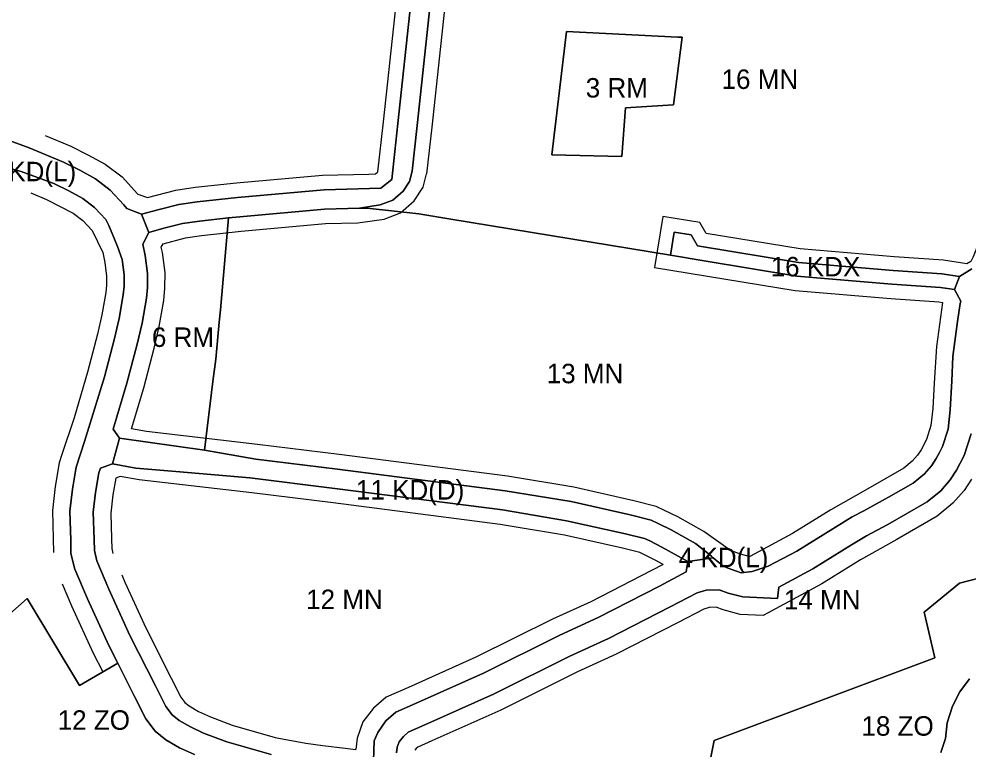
# Model space of a CAD drawing. Extents: x 7418056 to 7420315, y 5537846 to 5539505.
# Drawn here: x 7419326.3 to 7419814.6, y 5538250.2 to 5538625.8 of the extents above; entities that cross this region are included whole.
import ezdxf

# ---------------------------------------------------------------- set-up
doc = ezdxf.new("R2010")
doc.units = 0
for name, color, linetype in [('linie_rozgraniczajace', 7, 'Continuous'), ('linie_zabudowy_nieprzekraczalne', 7, 'Continuous'), ('oznaczenia_przeznaczen', 7, 'Continuous')]:
    doc.layers.add(name, color=color, linetype=linetype)

msp = doc.modelspace()

# ---------------------------------------------------------------- linework, layer by layer
at = {"layer": 'linie_rozgraniczajace'}
for points in [[(7419527.79, 5538634.11), (7419521.09, 5538572.08), (7419517.88, 5538543.33), (7419512.34, 5538538.77), (7419483.13, 5538538.02), (7419438.65, 5538534.06), (7419417.86, 5538531.87), (7419408.44, 5538530.44), (7419398.33, 5538527.89), (7419389.39, 5538525.51), (7419381.7, 5538528.33), (7419380.3, 5538530.33), (7419373.25, 5538537.88), (7419365.65, 5538543.65), (7419357.53, 5538548.07), (7419349.3, 5538552.2), (7419331.61, 5538559.58), (7419319.89, 5538563.81)], [(7419537.73, 5538633.12), (7419531.03, 5538570.98), (7419528.42, 5538547.57), (7419527.08, 5538542.33), (7419523.81, 5538537.29), (7419518.49, 5538532.76), (7419512.01, 5538530.22), (7419501.3, 5538528.51), (7419483.39, 5538528.1), (7419439.88, 5538524.14), (7419434.05, 5538523.53), (7419419.14, 5538521.95), (7419410.42, 5538520.63), (7419400.85, 5538518.22), (7419393.14, 5538516.15), (7419389.39, 5538525.51), (7419398.33, 5538527.89), (7419408.44, 5538530.44), (7419417.86, 5538531.87), (7419438.65, 5538534.06), (7419483.13, 5538538.02), (7419512.34, 5538538.77), (7419517.88, 5538543.33), (7419521.09, 5538572.08), (7419527.79, 5538634.11)], [(7419816.12, 5538497.47), (7419809.77, 5538493.53), (7419800.65, 5538494.85), (7419775.53, 5538496.55), (7419726.97, 5538500.67), (7419675.06, 5538509.2), (7419671.87, 5538514.79), (7419663.05, 5538516.24), (7419661.14, 5538504.39), (7419548.36, 5538522.9), (7419531.9, 5538525.73), (7419505.32, 5538528.6), (7419501.3, 5538528.51), (7419512.01, 5538530.22), (7419518.49, 5538532.76), (7419523.81, 5538537.29), (7419527.08, 5538542.33), (7419528.42, 5538547.57), (7419531.03, 5538570.98), (7419537.73, 5538633.12)], [(7419319.89, 5538563.81), (7419331.61, 5538559.58), (7419349.3, 5538552.2), (7419357.53, 5538548.07), (7419365.65, 5538543.65), (7419373.25, 5538537.88), (7419380.3, 5538530.33), (7419381.7, 5538528.33), (7419389.39, 5538525.51), (7419393.14, 5538516.15), (7419389.95, 5538510.08), (7419391.15, 5538504.22), (7419392.41, 5538495.02), (7419392.33, 5538487.87), (7419391.83, 5538482.39), (7419389.58, 5538469.57), (7419387.14, 5538458.78), (7419381.75, 5538438.65), (7419374.77, 5538414.95), (7419377.93, 5538410.33), (7419374.4, 5538397.3), (7419368.23, 5538395.05), (7419367.46, 5538392.63), (7419365.67, 5538382.53), (7419364.53, 5538372.33), (7419364.93, 5538358.39), (7419365.11, 5538352.68), (7419366.27, 5538347.32), (7419372.54, 5538332.83), (7419383.38, 5538309.09), (7419396.48, 5538283.12), (7419401.82, 5538272.56), (7419405.09, 5538268.27), (7419408.61, 5538265.4), (7419414.41, 5538262.07), (7419421.22, 5538258.92), (7419433.11, 5538254.43), (7419456, 5538247.89)], [(7419319.28, 5538549.7), (7419327.41, 5538547.33), (7419344.3, 5538541.28), (7419351.97, 5538537.44), (7419359.1, 5538533.54), (7419365.19, 5538528.94), (7419370.95, 5538522.77), (7419372.51, 5538519.59), (7419375.41, 5538512.72), (7419377.02, 5538508.93), (7419379.31, 5538502.19), (7419380.4, 5538494.26), (7419380.34, 5538488.49), (7419379.93, 5538483.99), (7419377.82, 5538471.94), (7419375.48, 5538461.66), (7419370.22, 5538441.95), (7419360.02, 5538408.78), (7419355.78, 5538395.51), (7419353.8, 5538384.25), (7419352.51, 5538372.83), (7419352.94, 5538357.98), (7419353.03, 5538351.16), (7419355.04, 5538343.09), (7419361.58, 5538327.95), (7419372.56, 5538303.89), (7419377.13, 5538294.83), (7419357.52, 5538283.4), (7419330.63, 5538328.03), (7419321.67, 5538320.2)], [(7419377.02, 5538508.93), (7419375.41, 5538512.72), (7419372.51, 5538519.59), (7419370.95, 5538522.77), (7419365.19, 5538528.94), (7419359.1, 5538533.54), (7419351.97, 5538537.44), (7419344.3, 5538541.28), (7419327.41, 5538547.33), (7419319.28, 5538549.7)], [(7419416.59, 5538247.84), (7419408.89, 5538251.39), (7419401.79, 5538255.48), (7419396.39, 5538259.87), (7419391.61, 5538266.17), (7419385.77, 5538277.7), (7419377.13, 5538294.83), (7419372.56, 5538303.89), (7419361.58, 5538327.95), (7419355.04, 5538343.09), (7419353.03, 5538351.16), (7419352.94, 5538357.98), (7419352.51, 5538372.83), (7419353.8, 5538384.25), (7419355.78, 5538395.51), (7419360.02, 5538408.78), (7419370.22, 5538441.95), (7419375.48, 5538461.66), (7419377.82, 5538471.94), (7419379.93, 5538483.99), (7419380.34, 5538488.49), (7419380.4, 5538494.26), (7419379.31, 5538502.19), (7419377.02, 5538508.93)], [(7419508.49, 5538244.87), (7419508.96, 5538254.97), (7419510.76, 5538259.2), (7419514.82, 5538265.23), (7419519.95, 5538269.69), (7419530.12, 5538274.07), (7419565.05, 5538289.7), (7419604.32, 5538309.27), (7419624.08, 5538318.3), (7419655.47, 5538334.4), (7419669.14, 5538341.69), (7419670.09, 5538347), (7419683.11, 5538349.01), (7419686.01, 5538346.45), (7419688.47, 5538344.71), (7419690.24, 5538343.81), (7419694.5, 5538342.24), (7419697.45, 5538341.16), (7419703.06, 5538341.87), (7419711.3, 5538344.6), (7419726.16, 5538352.38), (7419754.58, 5538369.95), (7419760.51, 5538373.06), (7419773.28, 5538380.11), (7419785.82, 5538387.21), (7419791.7, 5538392.08), (7419795.33, 5538396.17), (7419797.72, 5538399.94), (7419799.36, 5538403.03), (7419801.02, 5538406.18), (7419803.87, 5538415.05), (7419804.92, 5538424.9), (7419805.84, 5538439.71), (7419806.3, 5538452.3), (7419808.6, 5538470.27), (7419810.05, 5538479.58), (7419810.38, 5538480.79), (7419807.18, 5538486.83), (7419809.77, 5538493.53), (7419816.12, 5538497.47)], [(7419815.67, 5538412.56), (7419812.13, 5538401.51), (7419808.11, 5538393.91), (7419804.94, 5538388.92), (7419800.06, 5538383.43), (7419793.11, 5538377.67), (7419772.91, 5538366.07), (7419761.94, 5538360.3), (7419754.26, 5538355.62), (7419734.4, 5538343.29), (7419716.8, 5538333.85), (7419716.12, 5538327.99), (7419698.33, 5538328.82), (7419690.88, 5538330.79), (7419686.1, 5538332.54), (7419679.52, 5538332.38), (7419674.86, 5538330.96), (7419661.04, 5538323.77), (7419629.31, 5538307.5), (7419609.5, 5538298.43), (7419570.17, 5538278.85), (7419534.95, 5538263.08), (7419526.4, 5538259.41), (7419523.88, 5538257.21), (7419521.72, 5538254.42), (7419520.73, 5538251.65), (7419520.43, 5538248.74)], [(7419520.43, 5538248.74), (7419520.73, 5538251.65), (7419521.72, 5538254.42), (7419523.88, 5538257.21), (7419526.4, 5538259.41), (7419534.95, 5538263.08), (7419570.17, 5538278.85), (7419609.5, 5538298.43), (7419629.31, 5538307.5), (7419661.04, 5538323.77), (7419674.86, 5538330.96), (7419679.52, 5538332.38), (7419686.1, 5538332.54), (7419690.88, 5538330.79), (7419698.33, 5538328.82), (7419716.12, 5538327.99), (7419716.8, 5538333.85), (7419734.4, 5538343.29), (7419754.26, 5538355.62), (7419761.94, 5538360.3), (7419772.91, 5538366.07), (7419793.11, 5538377.67), (7419800.06, 5538383.43), (7419804.94, 5538388.92), (7419808.11, 5538393.91), (7419812.13, 5538401.51), (7419815.67, 5538412.56)], [(7419456, 5538247.89), (7419433.11, 5538254.43), (7419421.22, 5538258.92), (7419414.41, 5538262.07), (7419408.61, 5538265.4), (7419405.09, 5538268.27), (7419401.82, 5538272.56), (7419396.48, 5538283.12), (7419383.38, 5538309.09), (7419372.54, 5538332.83), (7419366.27, 5538347.32), (7419365.11, 5538352.68), (7419364.93, 5538358.39), (7419364.53, 5538372.33), (7419365.67, 5538382.53), (7419367.46, 5538392.63), (7419368.23, 5538395.05), (7419374.4, 5538397.3), (7419386.41, 5538395.06), (7419407.03, 5538393.34), (7419444.98, 5538389.96), (7419488.72, 5538384.61), (7419574.87, 5538373.52), (7419607.81, 5538367.98), (7419638.13, 5538361.28), (7419647.89, 5538358.81), (7419650.47, 5538357.58), (7419656.8, 5538354.43), (7419668.53, 5538347.88), (7419670.09, 5538347), (7419669.14, 5538341.69), (7419655.47, 5538334.4), (7419624.08, 5538318.3), (7419604.32, 5538309.27), (7419565.05, 5538289.7), (7419530.12, 5538274.07), (7419519.95, 5538269.69), (7419514.82, 5538265.23), (7419510.76, 5538259.2), (7419508.96, 5538254.97), (7419508.49, 5538244.87)], [(7419680.13, 5538237.77), (7419683.61, 5538255.16), (7419796.97, 5538297.57), (7419791.46, 5538320.98), (7419809.68, 5538335.84), (7419859.4, 5538348.83)], [(7419859.4, 5538348.83), (7419809.68, 5538335.84), (7419791.46, 5538320.98), (7419796.97, 5538297.57), (7419683.61, 5538255.16), (7419680.13, 5538237.77)], [(7419321.67, 5538320.2), (7419330.63, 5538328.03), (7419357.52, 5538283.4), (7419377.13, 5538294.83), (7419385.77, 5538277.7), (7419391.61, 5538266.17), (7419396.39, 5538259.87), (7419401.79, 5538255.48), (7419408.89, 5538251.39), (7419416.59, 5538247.84)], [(7419814.78, 5538286.82), (7419809.89, 5538280.17), (7419806.03, 5538272.71), (7419803.37, 5538264.15), (7419802.48, 5538256.12), (7419800.04, 5538248.99)], [(7419800.04, 5538248.99), (7419802.48, 5538256.12), (7419803.37, 5538264.15), (7419806.03, 5538272.71), (7419809.89, 5538280.17), (7419814.78, 5538286.82)]]:
    msp.add_lwpolyline(points, dxfattribs=at)
for points in [[(7419600.26, 5538556.04), (7419607.81, 5538619.27), (7419664.93, 5538616.41), (7419667.23, 5538616.34), (7419662.8, 5538581.6), (7419637.98, 5538580.13), (7419636.23, 5538555.2)], [(7419600.26, 5538556.04), (7419636.23, 5538555.2), (7419637.98, 5538580.13), (7419662.8, 5538581.6), (7419667.23, 5538616.34), (7419664.93, 5538616.41), (7419607.81, 5538619.27)], [(7419421.67, 5538404.21), (7419425.91, 5538439.45), (7419427.53, 5538450.93), (7419429.28, 5538469.98), (7419429.83, 5538476.31), (7419434.05, 5538523.53), (7419439.88, 5538524.14), (7419483.39, 5538528.1), (7419501.3, 5538528.51), (7419505.32, 5538528.6), (7419531.9, 5538525.73), (7419548.36, 5538522.9), (7419661.14, 5538504.39), (7419678.42, 5538501.55), (7419726.1, 5538493.72), (7419774.99, 5538489.57), (7419799.9, 5538487.88), (7419807.18, 5538486.83), (7419810.38, 5538480.79), (7419810.05, 5538479.58), (7419808.6, 5538470.27), (7419806.3, 5538452.3), (7419805.84, 5538439.71), (7419804.92, 5538424.9), (7419803.87, 5538415.05), (7419801.02, 5538406.18), (7419799.36, 5538403.03), (7419797.72, 5538399.94), (7419795.33, 5538396.17), (7419791.7, 5538392.08), (7419785.82, 5538387.21), (7419773.28, 5538380.11), (7419760.51, 5538373.06), (7419754.58, 5538369.95), (7419726.16, 5538352.38), (7419711.3, 5538344.6), (7419703.06, 5538341.87), (7419697.45, 5538341.16), (7419694.5, 5538342.24), (7419690.24, 5538343.81), (7419688.47, 5538344.71), (7419686.01, 5538346.45), (7419683.11, 5538349.01), (7419682.2, 5538349.83), (7419674.1, 5538356.23), (7419661.48, 5538363.28), (7419654.85, 5538366.57), (7419651.29, 5538368.27), (7419640.52, 5538370.99), (7419610.04, 5538377.8), (7419576.27, 5538383.43), (7419489.95, 5538394.53), (7419448.1, 5538399.64)], [(7419374.77, 5538414.95), (7419381.75, 5538438.65), (7419387.14, 5538458.78), (7419389.58, 5538469.57), (7419391.83, 5538482.39), (7419392.33, 5538487.87), (7419392.41, 5538495.02), (7419391.15, 5538504.22), (7419389.95, 5538510.08), (7419393.14, 5538516.15), (7419400.85, 5538518.22), (7419410.42, 5538520.63), (7419419.14, 5538521.95), (7419434.05, 5538523.53), (7419429.83, 5538476.31), (7419429.28, 5538469.98), (7419427.53, 5538450.93), (7419425.91, 5538439.45), (7419421.67, 5538404.21), (7419377.93, 5538410.33)], [(7419661.14, 5538504.39), (7419663.05, 5538516.24), (7419671.87, 5538514.79), (7419675.06, 5538509.2), (7419726.97, 5538500.67), (7419775.53, 5538496.55), (7419800.65, 5538494.85), (7419809.77, 5538493.53), (7419807.18, 5538486.83), (7419799.9, 5538487.88), (7419774.99, 5538489.57), (7419726.1, 5538493.72), (7419678.42, 5538501.55)], [(7419374.4, 5538397.3), (7419377.93, 5538410.33), (7419421.67, 5538404.21), (7419448.1, 5538399.64), (7419489.95, 5538394.53), (7419576.27, 5538383.43), (7419610.04, 5538377.8), (7419640.52, 5538370.99), (7419651.29, 5538368.27), (7419654.85, 5538366.57), (7419661.48, 5538363.28), (7419674.1, 5538356.23), (7419682.2, 5538349.83), (7419683.11, 5538349.01), (7419670.09, 5538347), (7419668.53, 5538347.88), (7419656.8, 5538354.43), (7419650.47, 5538357.58), (7419647.89, 5538358.81), (7419638.13, 5538361.28), (7419607.81, 5538367.98), (7419574.87, 5538373.52), (7419488.72, 5538384.61), (7419444.98, 5538389.96), (7419407.03, 5538393.34), (7419386.41, 5538395.06)]]:
    msp.add_lwpolyline(points, close=True, dxfattribs=at)
at = {"layer": 'linie_zabudowy_nieprzekraczalne'}
for points in [[(7419552.54, 5538721.2), (7419545.2, 5538632.41), (7419538.48, 5538570.17), (7419535.81, 5538546.23)], [(7419339.8, 5538565.92), (7419353.05, 5538560.39), (7419361.7, 5538556.05), (7419370.55, 5538551.23), (7419379.3, 5538544.59), (7419387.32, 5538536.01), (7419387.42, 5538535.82), (7419392.32, 5538534.02), (7419406.92, 5538537.8), (7419416.91, 5538539.32), (7419438.17, 5538541.56), (7419482.4, 5538545.59), (7419506.06, 5538546.12), (7419509.54, 5538546.19), (7419510.76, 5538547.2), (7419513.63, 5538572.9), (7419520.31, 5538634.78)], [(7419845.31, 5538593.55), (7419848.17, 5538593.31), (7419841.03, 5538565.71), (7419831.72, 5538538.31), (7419819.7, 5538510.97), (7419816.67, 5538503.53), (7419815.59, 5538501.16), (7419813.55, 5538500.05), (7419801.39, 5538501.82), (7419776.06, 5538503.53), (7419727.84, 5538507.63), (7419679.48, 5538515.57), (7419676.31, 5538521.13)], [(7419500.55, 5538520.99), (7419513.99, 5538522.95), (7419522.39, 5538526.24), (7419529.51, 5538532.29), (7419534.05, 5538539.29), (7419535.81, 5538546.23)], [(7419332.47, 5538536.47), (7419340.55, 5538533.1), (7419354.21, 5538525.97), (7419359.13, 5538522.23), (7419363.93, 5538517.1), (7419369.38, 5538505.86), (7419370.44, 5538500.68), (7419371.4, 5538493.7), (7419371.35, 5538488.95), (7419371, 5538485.18), (7419368.99, 5538473.72), (7419366.74, 5538463.83), (7419366.74, 5538463.83), (7419361.53, 5538444.33), (7419354.63, 5538420.89), (7419348.22, 5538401.43), (7419347.03, 5538397.67), (7419344.88, 5538385.55), (7419343.49, 5538373.21), (7419344.12, 5538351.65)], [(7419652.97, 5538498.14), (7419725.18, 5538486.28), (7419774.42, 5538482.1), (7419799.11, 5538480.42), (7419801.04, 5538480.14), (7419797.89, 5538457.55), (7419796.75, 5538438.63), (7419795.95, 5538425.66), (7419795.02, 5538416.93), (7419792.7, 5538409.69), (7419789.94, 5538404.48), (7419788.12, 5538401.61), (7419785.42, 5538398.57), (7419781.1, 5538394.99), (7419762.62, 5538384.38), (7419743.49, 5538373.65), (7419723.89, 5538361.48), (7419701.88, 5538349.68), (7419701.54, 5538349.69), (7419697.2, 5538350.84), (7419692.01, 5538352.75), (7419678.28, 5538362.48), (7419664.98, 5538369.91), (7419658.13, 5538373.32), (7419653.84, 5538375.36), (7419642.26, 5538378.29), (7419611.47, 5538385.17), (7419577.36, 5538390.85), (7419490.89, 5538401.98), (7419448.98, 5538407.1), (7419391.83, 5538413.75), (7419384.2, 5538415.12), (7419390.42, 5538436.22), (7419395.87, 5538456.63), (7419398.41, 5538467.8), (7419400.76, 5538481.21), (7419401.33, 5538487.41), (7419401.42, 5538495.59), (7419400.02, 5538505.74), (7419399.44, 5538508.57), (7419400.43, 5538510.3), (7419411.94, 5538513.28), (7419420.09, 5538514.51), (7419440.61, 5538516.68), (7419483.82, 5538520.62), (7419500.55, 5538520.99)], [(7419676.31, 5538521.13), (7419657.19, 5538524.31), (7419652.97, 5538498.14)], [(7419657.36, 5538345.53), (7419653.3, 5538347.8), (7419647.19, 5538350.84), (7419645.33, 5538351.73), (7419636.46, 5538353.97), (7419606.69, 5538360.62), (7419573.71, 5538366.11), (7419487.78, 5538377.17), (7419446.02, 5538382.27), (7419388.17, 5538389.01), (7419378.34, 5538390.77), (7419376.12, 5538389.94), (7419374.59, 5538381.25), (7419373.54, 5538371.96), (7419373.93, 5538358.67), (7419374.07, 5538353.79), (7419374.65, 5538351.15)], [(7419815.89, 5538389.39), (7419812.14, 5538383.49), (7419806.33, 5538376.94), (7419798.26, 5538370.26), (7419777.42, 5538358.29), (7419758.74, 5538347.82), (7419738.91, 5538335.49), (7419708.76, 5538319.33), (7419696.96, 5538319.88), (7419688.17, 5538322.2), (7419684.61, 5538323.51), (7419680.98, 5538323.42), (7419678.27, 5538322.59), (7419665.17, 5538315.78), (7419633.24, 5538299.4), (7419613.38, 5538290.32), (7419574.02, 5538270.71), (7419538.57, 5538254.84), (7419531.25, 5538251.7), (7419530.45, 5538251), (7419529.72, 5538250.06)], [(7419657.36, 5538345.53), (7419651.4, 5538342.43), (7419620.15, 5538326.4), (7419600.45, 5538317.39), (7419561.2, 5538297.84), (7419526.51, 5538282.31), (7419515.11, 5538277.41), (7419508.56, 5538271.72), (7419503.05, 5538264.62), (7419500.12, 5538256.33), (7419499.5, 5538250.49)], [(7419379.19, 5538340.13), (7419380.77, 5538336.49), (7419391.5, 5538312.99), (7419404.52, 5538287.17), (7419409.48, 5538277.36), (7419411.6, 5538274.57), (7419413.73, 5538272.84), (7419418.54, 5538270.07), (7419424.7, 5538267.23), (7419435.95, 5538262.99), (7419458.06, 5538256.67), (7419473.75, 5538253.78), (7419482.43, 5538252.51), (7419494.05, 5538251.17), (7419499.5, 5538250.49)], [(7419348.45, 5538335.65), (7419353.35, 5538324.31), (7419364.45, 5538300), (7419369.35, 5538290.29)], [(7419377.74, 5538273.65), (7419377.74, 5538273.65)]]:
    msp.add_lwpolyline(points, dxfattribs=at)

# ---------------------------------------------------------------- texts
at = {"layer": 'oznaczenia_przeznaczen'}
for s, p in [('16 MN', (7419687.4, 5538589.82)), ('3 RM', (7419617.61, 5538585.4)), ('3 KD(L)', (7419309.69, 5538542.4)), ('16 KDX', (7419712.65, 5538493.52)), ('6 RM', (7419394.65, 5538457.28)), ('13 MN', (7419597.54, 5538438.62)), ('11 KD(D)', (7419499.5, 5538378.85)), ('4 KD(L)', (7419665.4, 5538344.09)), ('12 MN', (7419473.92, 5538322.62)), ('14 MN', (7419719.43, 5538322.45)), ('12 ZO', (7419346.22, 5538260.6)), ('18 ZO', (7419759.3, 5538257.56))]:
    msp.add_text(s, height=10, dxfattribs=at).set_placement(p)

doc.saveas('drawing.dxf')
